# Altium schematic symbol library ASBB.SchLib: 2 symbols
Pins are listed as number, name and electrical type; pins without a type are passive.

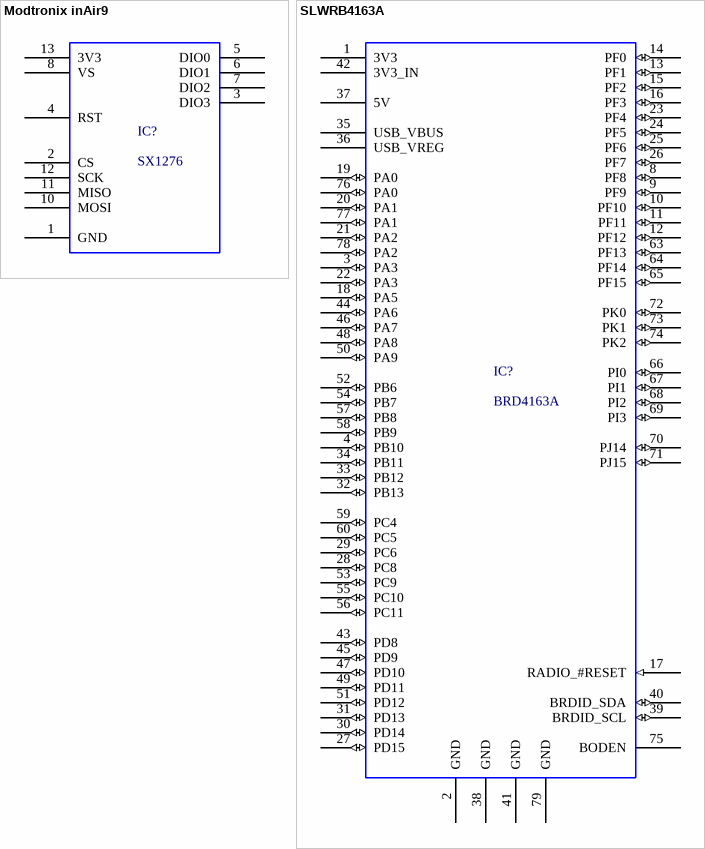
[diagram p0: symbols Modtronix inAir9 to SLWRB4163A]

## Modtronix inAir9
designator IC?, comment SX1276
Modtronix LoRa Transceiver
footprint Modtronix inAir9
pins: 1 GND (power), 2 CS (power), 3 DIO3 (power), 4 RST (power), 5 DIO0 (power), 6 DIO1 (power), 7 DIO2 (power), 8 VS (power), 9 NC (power) hidden, 10 MOSI (power), 11 MISO (power), 12 SCK (power), 13 3V3 (power), 14 NC (power) hidden

## SLWRB4163A
designator IC?, comment BRD4163A
footprint 80-Pin SiLabs Module (Pin Header, pitch 1.27 mm, SMD, Vertical, dual row, 50p)
pins: 1 3V3 (power), 2 GND (power), 3 PA3 (io), 4 PB10 (io), 5 NC (power) hidden, 6 NC (power) hidden, 7 NC (power) hidden, 8 PF8 (io), 9 PF9 (io), 10 PF10 (io), 11 PF11 (io), 12 PF12 (io), 13 PF1 (io), 14 PF0 (io), 15 PF2 (io), 16 PF3 (io), 17 RADIO_#RESET (in), 18 PA5 (io), 19 PA0 (io), 20 PA1 (io), 21 PA2 (io), 22 PA3 (io), 23 PF4 (io), 24 PF5 (io), 25 PF6 (io), 26 PF7 (io), 27 PD15 (io), 28 PC8 (io), 29 PC6 (io), 30 PD14 (io), 31 PD13 (io), 32 PB13 (io), 33 PB12 (io), 34 PB11 (io), 35 USB_VBUS (power), 36 USB_VREG (power), 37 5V (power), 38 GND (power), 39 BRDID_SCL (io), 40 BRDID_SDA (io), 41 GND (power), 42 3V3_IN (power), 43 PD8 (io), 44 PA6 (io), 45 PD9 (io), 46 PA7 (io), 47 PD10 (io), 48 PA8 (io), 49 PD11 (io), 50 PA9 (io), 51 PD12 (io), 52 PB6 (io), 53 PC9 (io), 54 PB7 (io), 55 PC10 (io), 56 PC11 (io), 57 PB8 (io), 58 PB9 (io), 59 PC4 (io), 60 PC5 (io), 61 NC (power) hidden, 62 NC (power) hidden, 63 PF13 (io), 64 PF14 (io), 65 PF15 (io), 66 PI0 (io), 67 PI1 (io), 68 PI2 (io), 69 PI3 (io), 70 PJ14 (io), 71 PJ15 (io), 72 PK0 (io), 73 PK1 (io), 74 PK2 (io), 75 BODEN (power), 76 PA0 (io), 77 PA1 (io), 78 PA2 (io), 79 GND (power), 80 NC (power) hidden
